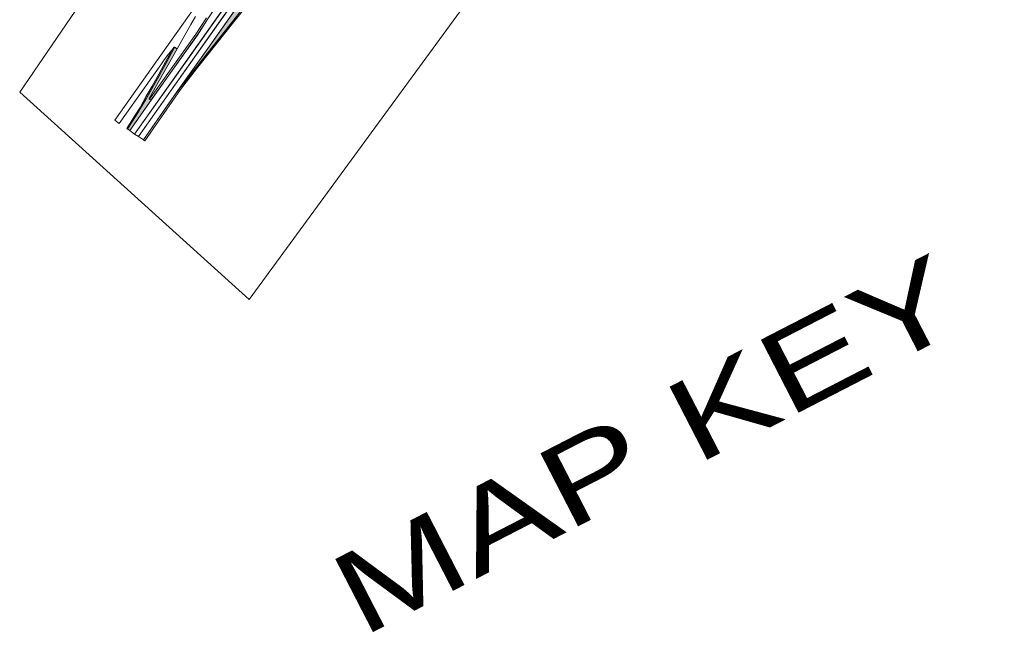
# Model space of a CAD drawing. Extents: x 2356431 to 2371438, y 6972864 to 6982525.
# Drawn here: x 2370359.1 to 2370623.6, y 6981228 to 6981390.9 of the extents above; entities that cross this region are included whole.
import ezdxf

# ---------------------------------------------------------------- set-up
doc = ezdxf.new("R2010")
doc.units = 0
doc.header["$LTSCALE"] = 5.6
for name, color, linetype, lineweight in [('1', 7, 'Continuous', 25), ('10', 7, 'Continuous', 13), ('11', 7, 'Continuous', 13), ('62', 7, 'Continuous', 25), ('9', 7, 'Continuous', 13)]:
    doc.layers.add(name, color=color, linetype=linetype, lineweight=lineweight)

msp = doc.modelspace()

# ---------------------------------------------------------------- hatches: boundary and pattern name
at = {"layer": '10'}
msp.add_hatch(color=256, dxfattribs=at).paths.add_polyline_path([(2370387.488, 6981362.051), (2370389.553, 6981365.28), (2370391.053, 6981367.65), (2370392.668, 6981370.586), (2370394.237, 6981373.324), (2370396.055, 6981376.487), (2370397.854, 6981379.757), (2370399.664, 6981383.11), (2370400.126, 6981383.712), (2370400.251, 6981383.625), (2370399.005, 6981381.356), (2370396.003, 6981375.879), (2370392.733, 6981370.081), (2370391.52, 6981367.926), (2370390.192, 6981365.805), (2370387.719, 6981361.882)])
at = {"layer": '11'}
for points in [[(2370419.056, 6981394.804), (2370417.807, 6981395.688), (2370409.071, 6981383.337), (2370400.626, 6981371.515)], [(2370400.874, 6981383.24), (2370393.449, 6981370.009), (2370393.473, 6981369.835), (2370394.025, 6981369.562), (2370388.304, 6981361.488), (2370387.709, 6981361.898), (2370389.842, 6981365.221), (2370390.886, 6981366.873), (2370391.695, 6981368.319), (2370392.465, 6981369.573), (2370393.262, 6981370.968), (2370398.1, 6981379.601), (2370400.207, 6981383.55)]]:
    msp.add_hatch(color=256, dxfattribs=at).paths.add_polyline_path(points)

# ---------------------------------------------------------------- linework, layer by layer
at = {"layer": '1', "lineweight": 13}
msp.add_lwpolyline([(2370359.058, 6981371.686), (2370521.887, 6981610.181), (2370526.335, 6981821.134), (2370603.448, 6981839.65), (2370623.649, 6981594.663), (2370420.032, 6981316.493)], close=True, dxfattribs=at)
at = {"layer": '10'}
for points in [[(2370502.07, 6981521.401), (2370503.399, 6981522.837), (2370504.782, 6981524.332), (2370507.283, 6981526.965), (2370498.731, 6981514.811), (2370491.472, 6981504.557), (2370389.594, 6981360.507), (2370388.304, 6981361.488), (2370394.025, 6981369.562), (2370406.452, 6981387.148), (2370413.815, 6981398.493), (2370439.499, 6981434.83), (2370446.459, 6981445.125), (2370451.934, 6981453.981), (2370452.933, 6981453.485), (2370453.674, 6981452.979)], [(2370389.594, 6981360.506), (2370403.112, 6981379.577), (2370416.673, 6981398.861), (2370436.092, 6981426.283), (2370455.306, 6981453.47), (2370469.701, 6981473.822), (2370481.401, 6981490.343), (2370491.266, 6981504.411), (2370491.807, 6981503.284), (2370484.764, 6981492.889), (2370481.708, 6981488.194), (2370469.195, 6981470.906), (2370452.703, 6981447.859), (2370436.819, 6981425.42), (2370390.583, 6981359.884)], [(2370445.874, 6981438.034), (2370421.028, 6981402.946), (2370408.428, 6981385.09), (2370404.097, 6981378.931), (2370390.615, 6981359.897), (2370391.946, 6981358.975), (2370400.626, 6981371.515), (2370409.071, 6981383.337), (2370435.892, 6981421.274), (2370436.872, 6981422.595), (2370441.02, 6981427.852), (2370447.889, 6981436.451)], [(2370387.488, 6981362.051), (2370389.553, 6981365.28), (2370391.053, 6981367.65), (2370392.668, 6981370.586), (2370394.237, 6981373.324), (2370396.055, 6981376.487), (2370397.854, 6981379.757), (2370399.664, 6981383.11), (2370400.126, 6981383.712), (2370400.251, 6981383.625), (2370399.005, 6981381.356), (2370396.003, 6981375.879), (2370392.733, 6981370.081), (2370391.52, 6981367.926), (2370390.192, 6981365.805), (2370387.719, 6981361.882)]]:
    msp.add_lwpolyline(points, close=True, dxfattribs=at)
for points in [[(2370411.783, 6981395.389), (2370408.72, 6981390.651), (2370406.294, 6981386.885), (2370394.019, 6981369.611), (2370393.541, 6981369.815), (2370398.473, 6981376.618), (2370401.123, 6981380.401), (2370405.903, 6981387.114), (2370408.725, 6981391.453)], [(2370419.334, 6981394.553), (2370416.335, 6981390.816), (2370406.084, 6981377.862), (2370401.779, 6981372.386), (2370392.321, 6981358.726), (2370391.968, 6981358.983), (2370400.519, 6981371.357), (2370403.067, 6981374.591), (2370404.276, 6981376.141), (2370409.256, 6981382.419), (2370419.071, 6981394.814)]]:
    msp.add_lwpolyline(points, dxfattribs=at)
at = {"layer": '11'}
for points in [[(2370419.056, 6981394.804), (2370417.807, 6981395.688), (2370409.071, 6981383.337), (2370400.626, 6981371.515)], [(2370400.874, 6981383.24), (2370393.449, 6981370.009), (2370393.473, 6981369.835), (2370394.025, 6981369.562), (2370388.304, 6981361.488), (2370387.709, 6981361.898), (2370389.842, 6981365.221), (2370390.886, 6981366.873), (2370391.695, 6981368.319), (2370392.465, 6981369.573), (2370393.262, 6981370.968), (2370398.1, 6981379.601), (2370400.207, 6981383.55)]]:
    msp.add_lwpolyline(points, close=True, dxfattribs=at)
at = {"layer": '9'}
msp.add_lwpolyline([(2370405.783, 6981391.796), (2370404.509, 6981389.716), (2370400.874, 6981383.24), (2370400.165, 6981383.645), (2370400.148, 6981383.652), (2370400.132, 6981383.658), (2370400.113, 6981383.658), (2370400.099, 6981383.657), (2370400.079, 6981383.65), (2370400.064, 6981383.642), (2370400.044, 6981383.62), (2370399.817, 6981383.326), (2370398.268, 6981381.322), (2370397.285, 6981380.059), (2370396.562, 6981379.003), (2370385.516, 6981363.39), (2370384.34, 6981364.221), (2370487.022, 6981509.443)], dxfattribs=at)

# ---------------------------------------------------------------- texts
at = {"layer": '62', "width": 1.4}
msp.add_text('MAP KEY', height=21.87, rotation=27.268, dxfattribs=at).set_placement((2370450.041, 6981226.468))

doc.saveas('drawing.dxf')
